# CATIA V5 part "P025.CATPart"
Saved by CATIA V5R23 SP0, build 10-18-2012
Part number: 05-LICP-T02-E-S07-P025
Definition: Bague
Description: Bague
Bounding box of the stored display mesh (mm): x 0 to 28.5, y -9 to 9, z -8.951 to 8.951
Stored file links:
  C:\wamp\www\COURS\CONCEPTION GMP1\TITRE 02-SEMESTRE 2\03-TP7-PRESSE MECANIQUE\eleve\P025.CATPart
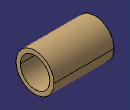
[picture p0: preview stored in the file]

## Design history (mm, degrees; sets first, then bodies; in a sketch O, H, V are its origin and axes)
Body1 (main body)
  Sketch1 on yz-plane, origin (0, 0, 0), H (0, 1, 0), V (0, 0, 1)
    circle A1 centre (0, 0) radius 9
    circle A2 centre (0, 0) radius 7
    radius A2 = 7
    radius A1 = 9
  Pad1: profile Sketch1, direction (1, 0, 0), length 28.5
